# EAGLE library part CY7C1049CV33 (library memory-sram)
4-Mbit (512K x 8) Static RAM Source: CYPRESS cy7c1049cv33_8.pdf
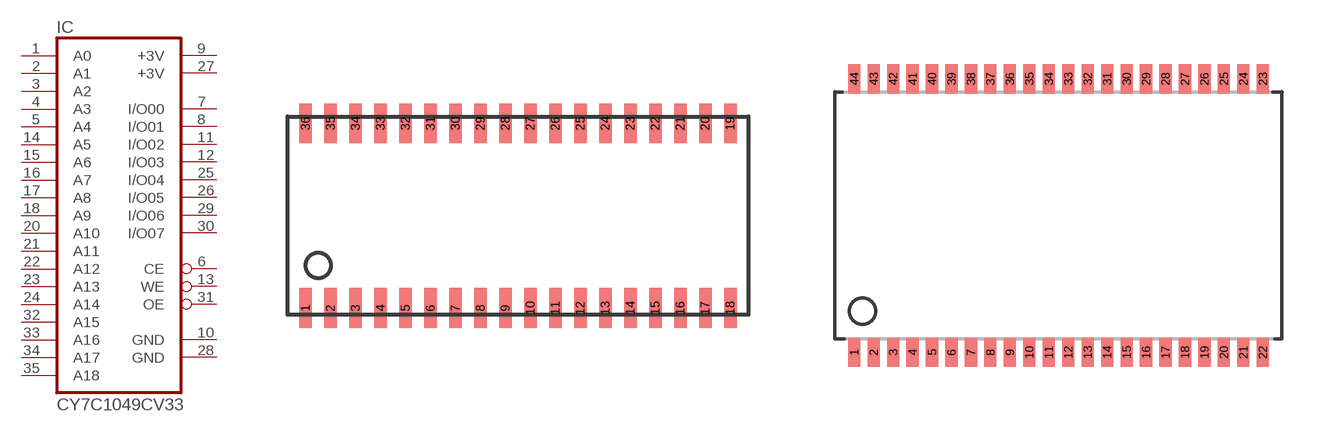
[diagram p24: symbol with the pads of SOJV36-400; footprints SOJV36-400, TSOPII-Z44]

Designator prefix IC

## CY7C1049CV33  [SOJV36-400]
1  A0  in
2  A1  in
3  A2  in
4  A3  in
5  A4  in
6  CE  in
7  I/O00
8  I/O01
9  +3V  pwr
10  GND  pwr
11  I/O02
12  I/O03
13  WE  in
14  A5  in
15  A6  in
16  A7  in
17  A8  in
18  A9  in
20  A10  in
21  A11  in
22  A12  in
23  A13  in
24  A14  in
25  I/O04
26  I/O05
27  +3V  pwr
28  GND  pwr
29  I/O06
30  I/O07
31  OE  in
32  A15  in
33  A16  in
34  A17  in
35  A18  in

## CY7C1049CV33T  [TSOPII-Z44]
3  A0  in
4  A1  in
5  A2  in
6  A3  in
7  A4  in
8  CE  in
9  I/O00
10  I/O01
11  +3V  pwr
12  GND  pwr
13  I/O02
14  I/O03
15  WE  in
16  A5  in
17  A6  in
18  A7  in
19  A8  in
20  A9  in
26  A10  in
27  A11  in
28  A12  in
29  A13  in
30  A14  in
31  I/O04
32  I/O05
33  +3V  pwr
34  GND  pwr
35  I/O06
36  I/O07
37  OE  in
38  A15  in
39  A16  in
40  A17  in
41  A18  in

## Footprint SOJV36-400 (pad centres in mm)
36-Lead (400-Mil) Molded SOJ V36 Source: CYPRESS cy7c1049cv33_8.pdf
smd 0.635 x 2.032: 1 -10.795,-4.699; 2 -9.525,-4.699; 3 -8.255,-4.699; 4 -6.985,-4.699; 5 -5.715,-4.699; 6 -4.445,-4.699; 7 -3.175,-4.699; 8 -1.905,-4.699; 9 -0.635,-4.699; 10 0.635,-4.699; 11 1.905,-4.699; 12 3.175,-4.699; 13 4.445,-4.699; 14 5.715,-4.699; 15 6.985,-4.699; 16 8.255,-4.699; 17 9.525,-4.699; 18 10.795,-4.699; 19 10.795,4.699; 20 9.525,4.699; 21 8.255,4.699; 22 6.985,4.699; 23 5.715,4.699; 24 4.445,4.699; 25 3.175,4.699; 26 1.905,4.699; 27 0.635,4.699; 28 -0.635,4.699; 29 -1.905,4.699; 30 -3.175,4.699; 31 -4.445,4.699; 32 -5.715,4.699; 33 -6.985,4.699; 34 -8.255,4.699; 35 -9.525,4.699; 36 -10.795,4.699

## Footprint TSOPII-Z44 (pad centres in mm)
44 PIN TSOP II Z44 Source: CYPRESS cy7c1049cv33_8.pdf
smd 0.5 x 1.2: 1 -8.4,-5.627; 2 -7.6,-5.627; 3 -6.8,-5.627; 4 -6,-5.627; 5 -5.2,-5.627; 6 -4.4,-5.627; 7 -3.6,-5.627; 8 -2.8,-5.627; 9 -2,-5.627; 10 -1.2,-5.627; 11 -0.4,-5.627; 12 0.4,-5.627; 13 1.2,-5.627; 14 2,-5.627; 15 2.8,-5.627; 16 3.6,-5.627; 17 4.4,-5.627; 18 5.2,-5.627; 19 6,-5.627; 20 6.8,-5.627; 21 7.6,-5.627; 22 8.4,-5.627; 23 8.4,5.627; 24 7.6,5.627; 25 6.8,5.627; 26 6,5.627; 27 5.2,5.627; 28 4.4,5.627; 29 3.6,5.627; 30 2.8,5.627; 31 2,5.627; 32 1.2,5.627; 33 0.4,5.627; 34 -0.4,5.627; 35 -1.2,5.627; 36 -2,5.627; 37 -2.8,5.627; 38 -3.6,5.627; 39 -4.4,5.627; 40 -5.2,5.627; 41 -6,5.627; 42 -6.8,5.627; 43 -7.6,5.627; 44 -8.4,5.627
